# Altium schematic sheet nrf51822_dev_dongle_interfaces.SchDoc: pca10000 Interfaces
size A4; Revision: 2.0.0; SheetNumber: 3; SheetTotal: 3; DrawnBy: RUBR; ProjectNumber: 4393; PCBRevision: 0100RUBR; DocumentSize: A4; PCAName: PCA10000; PCBNumber: 400003
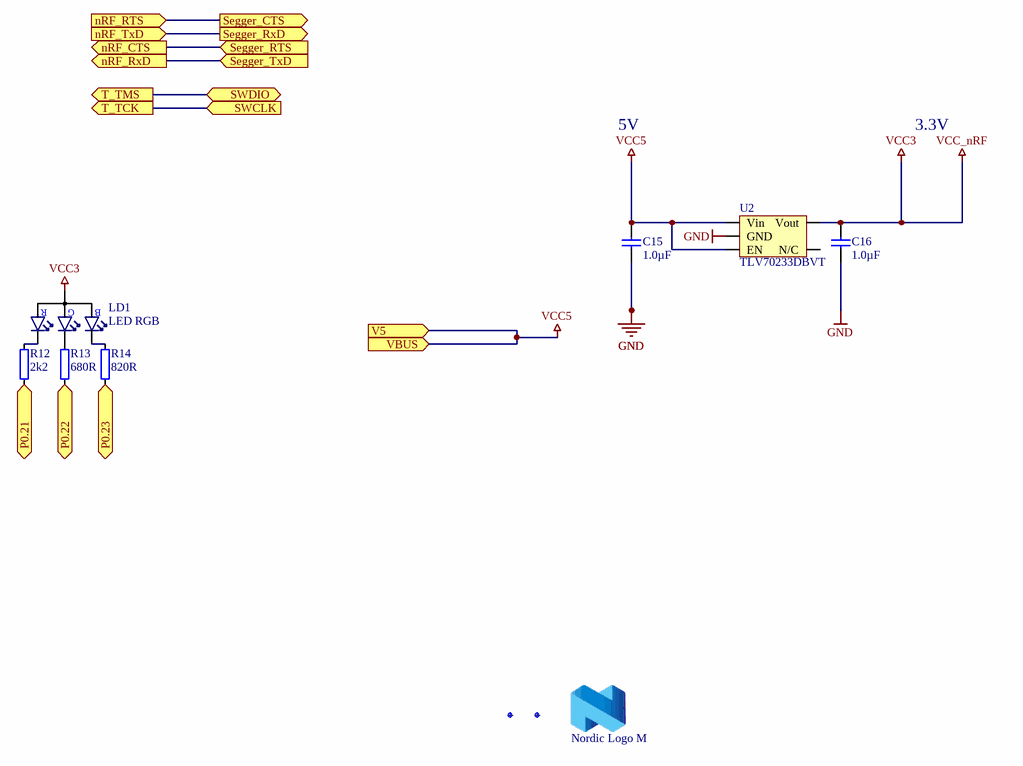
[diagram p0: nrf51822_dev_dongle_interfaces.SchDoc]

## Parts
C15  1.0µF  [CAPC1608X06L]
C16  1.0µF  [CAPC1608X06L]
Fid1  Fiducial mark  [Fiducial]  (value not drawn)
Fid2  Fiducial mark  [Fiducial]  (value not drawn)
LD1  LED RGB  [SML-LX0404SIUPGUSB]
LOGO1  Nordic Logo M  [NORDIC_LOGO_M]  (no BOM)
R12  2k2  [RESC1005X04L]
R13  680R  [RESC1005X04L]
R14  820R  [RESC1005X04L]
U2  TLV70233DBVT  [SOT-23-5]

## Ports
nRF_CTS (out), nRF_RTS (in), nRF_RxD (out), nRF_TxD (in), P0.21 (bidir), P0.22 (bidir), P0.23 (bidir), Segger_CTS (out), Segger_RTS (in), Segger_RxD (out), Segger_TxD (in), SWCLK (in), SWDIO (bidir), T_TCK (out), T_TMS (out), V5 (in), VBUS (in)

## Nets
GND: C15.1 C16.1 U2.2(GND)
VCC3: C16.2 LD1.4(A) U2.5(Vout)  [also labelled VCC_nRF]
VCC5: C15.2 U2.1(Vin) U2.3(EN) ; port V5, port VBUS
nRF_CTS: port Segger_RTS, port nRF_CTS
nRF_RTS: port Segger_CTS, port nRF_RTS
nRF_RxD: port Segger_TxD, port nRF_RxD
nRF_TxD: port Segger_RxD, port nRF_TxD
P0.21: R12.1 ; port P0.21
P0.22: R13.1 ; port P0.22
P0.23: R14.1 ; port P0.23
SWCLK: port T_TCK, port SWCLK
SWDIO: port T_TMS, port SWDIO
NetLD1_1: LD1.1(C_RED) R12.2
NetLD1_2: LD1.2(C_GREEN) R13.2
NetLD1_3: LD1.3(C_BLUE) R14.2

Not connected (* = marked no-connect by the designer): U2 4(N/C)

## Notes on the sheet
- 5V
- 3.3V

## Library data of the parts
C15 C16 = C0603-1µ0: Capacitor, X5R, ±10%; Note: 10V; Artikkelnr Noca: 20039205
Fid1 Fid2 = Fid-Mark: Artikkelnr Noca: N.A.
LD1 = SML-LX0404SIUPGUSB: RGB LED 1.00 mm x 1.00 mm SMD; Manufacturer: Lumex; 2nd source part number: 211-8843; Artikkelnr Noca: N.A.
LOGO1 = Nordic Logo M: Nordic Logo, medium size; Artikkelnr Noca: N.A.
R12 = R0402-2k2: Resistor, ±1%, 0.063W; Note: Chip Res 1%; Artikkelnr Noca: 27049081
R13 = R0402-680: Resistor, ±1%, 0.063W; Note: Chip Res 1%; Artikkelnr Noca: 27049069
R14 = R0402-820: Resistor, ±1%, 0.063W; Note: Chip Res 1%; Artikkelnr Noca: 27049071
U2 = TLV70233DBVT: IC REG LDO 3.3V 300MA SOT23-5; Manufacturer: Texas Instruments; Note: 300-mA, Low-IQ, Low-Dropout Regulator; Artikkelnr Noca: 17039215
